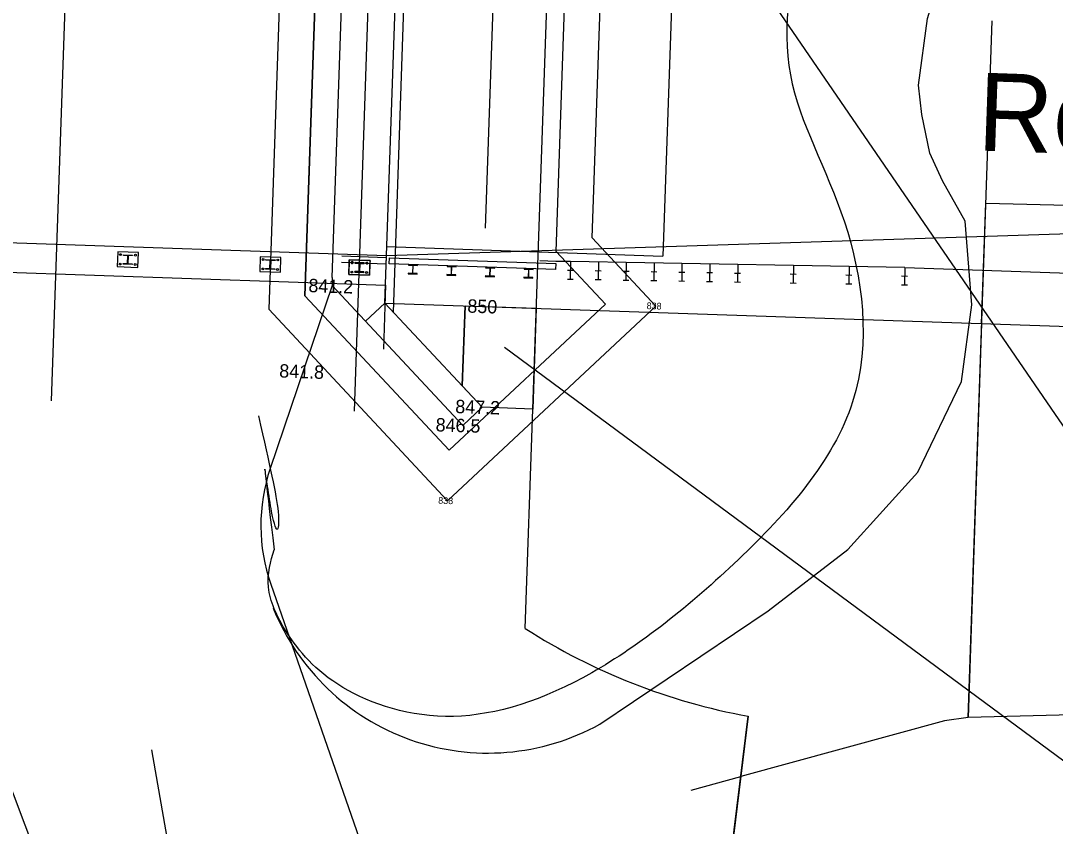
# Model space of a CAD drawing. Extents: x 2191309 to 2193046, y 863659 to 865133.
# Drawn here: x 2192668.4 to 2192726.5, y 863882.5 to 863927.7 of the extents above; entities that cross this region are included whole.
import ezdxf

# ---------------------------------------------------------------- set-up
doc = ezdxf.new("R2010")
doc.units = 0
for name, color, linetype in [('ANNOTATION', 7, 'Continuous'), ('D_Bridge_Abutment', 7, 'Continuous'), ('D_Bridge_Deck', 7, 'Continuous'), ('D_Bridge_Railing', 7, 'Continuous'), ('D_Bridge_Substructure_Hidden', 7, 'Continuous'), ('D_Guardrail_Beam_Lt', 7, 'Continuous'), ('D_Guardrail_Beam_Rt', 7, 'Continuous'), ('D_Roadway_Edge_Shoulder', 7, 'Continuous'), ('D_Roadway_Edge_TW', 7, 'Continuous'), ('D_Slope_Direction', 7, 'Continuous'), ('D_Slope_Toe', 7, 'Continuous'), ('DIMENSIONS', 7, 'Continuous'), ('H_V CONTROLS', 7, 'Continuous'), ('JUNK', 7, 'Continuous'), ('PATTERNING', 7, 'Continuous')]:
    doc.layers.add(name, color=color, linetype=linetype)

msp = doc.modelspace()

# ---------------------------------------------------------------- linework, layer by layer
at = {"layer": 'ANNOTATION'}
msp.add_line((2192706.024, 863884.486), (2192708.811, 863885.248), dxfattribs=at)
at = {"layer": 'D_Bridge_Abutment'}
for p, q in [((2192688.846, 863911.811), (2192690.012, 863945.791)), ((2192685.894, 863913.247), (2192685.878, 863912.792)), ((2192685.878, 863912.792), (2192693.209, 863904.94)), ((2192687.75, 863910.788), (2192688.846, 863911.811)), ((2192688.846, 863911.811), (2192694.306, 863905.964)), ((2192693.209, 863904.94), (2192694.306, 863905.964))]:
    msp.add_line(p, q, dxfattribs=at)
at = {"layer": 'D_Bridge_Deck'}
for p, q in [((2192651.959, 863915.745), (2192688.938, 863914.476)), ((2192651.902, 863914.08), (2192688.88, 863912.811))]:
    msp.add_line(p, q, dxfattribs=at)
at = {"layer": 'D_Bridge_Railing'}
for p, q in [((2192674.174, 863914.488), (2192674.175, 863914.525)), ((2192674.385, 863914.481), (2192674.174, 863914.488)), ((2192674.175, 863914.525), (2192674.685, 863914.507)), ((2192674.401, 863914.053), (2192674.415, 863914.449)), ((2192674.441, 863914.448), (2192674.427, 863914.052)), ((2192674.684, 863914.471), (2192674.473, 863914.478)), ((2192674.685, 863914.507), (2192674.684, 863914.471)), ((2192674.157, 863913.994), (2192674.158, 863914.03)), ((2192674.667, 863913.976), (2192674.157, 863913.994)), ((2192674.158, 863914.03), (2192674.37, 863914.023)), ((2192674.457, 863914.02), (2192674.668, 863914.013)), ((2192674.668, 863914.013), (2192674.667, 863913.976)), ((2192682.169, 863914.214), (2192682.171, 863914.25)), ((2192682.381, 863914.206), (2192682.169, 863914.214)), ((2192682.171, 863914.25), (2192682.681, 863914.233)), ((2192682.397, 863913.778), (2192682.41, 863914.175)), ((2192682.436, 863914.174), (2192682.423, 863913.777)), ((2192682.679, 863914.196), (2192682.468, 863914.203)), ((2192682.681, 863914.233), (2192682.679, 863914.196)), ((2192687.166, 863914.042), (2192687.168, 863914.079)), ((2192687.378, 863914.035), (2192687.166, 863914.042)), ((2192687.17, 863914.079), (2192687.168, 863914.041)), ((2192687.168, 863914.079), (2192687.678, 863914.061)), ((2192687.168, 863914.041), (2192687.378, 863914.034)), ((2192687.676, 863914.061), (2192687.17, 863914.079)), ((2192687.407, 863914.003), (2192687.393, 863913.607)), ((2192687.394, 863913.607), (2192687.407, 863914.003)), ((2192687.42, 863913.606), (2192687.434, 863914.002)), ((2192687.433, 863914.002), (2192687.42, 863913.606)), ((2192687.464, 863914.031), (2192687.675, 863914.023)), ((2192687.677, 863914.025), (2192687.465, 863914.032)), ((2192687.675, 863914.023), (2192687.676, 863914.061)), ((2192687.678, 863914.061), (2192687.677, 863914.025)), ((2192690.168, 863913.976), (2192690.166, 863913.938)), ((2192690.166, 863913.938), (2192690.377, 863913.931)), ((2192690.674, 863913.958), (2192690.168, 863913.976)), ((2192690.405, 863913.9), (2192690.392, 863913.504)), ((2192690.418, 863913.503), (2192690.432, 863913.899)), ((2192690.463, 863913.928), (2192690.673, 863913.92)), ((2192690.673, 863913.92), (2192690.674, 863913.958)), ((2192692.333, 863913.901), (2192692.332, 863913.863)), ((2192692.332, 863913.863), (2192692.542, 863913.856)), ((2192692.84, 863913.884), (2192692.333, 863913.901)), ((2192692.571, 863913.825), (2192692.557, 863913.429)), ((2192692.584, 863913.429), (2192692.597, 863913.825)), ((2192692.628, 863913.853), (2192692.838, 863913.846)), ((2192692.838, 863913.846), (2192692.84, 863913.884)), ((2192694.499, 863913.827), (2192694.497, 863913.789)), ((2192695.005, 863913.81), (2192694.499, 863913.827)), ((2192695.004, 863913.772), (2192695.005, 863913.81)), ((2192682.152, 863913.719), (2192682.154, 863913.756)), ((2192682.662, 863913.702), (2192682.152, 863913.719)), ((2192682.154, 863913.756), (2192682.365, 863913.748)), ((2192682.453, 863913.745), (2192682.664, 863913.738)), ((2192682.664, 863913.738), (2192682.662, 863913.702)), ((2192687.149, 863913.548), (2192687.151, 863913.584)), ((2192687.66, 863913.53), (2192687.149, 863913.548)), ((2192687.153, 863913.585), (2192687.151, 863913.547)), ((2192687.151, 863913.584), (2192687.362, 863913.577)), ((2192687.151, 863913.547), (2192687.658, 863913.53)), ((2192687.363, 863913.578), (2192687.153, 863913.585)), ((2192687.659, 863913.568), (2192687.449, 863913.575)), ((2192687.45, 863913.574), (2192687.661, 863913.567)), ((2192687.658, 863913.53), (2192687.659, 863913.568)), ((2192687.661, 863913.567), (2192687.66, 863913.53)), ((2192690.151, 863913.482), (2192690.15, 863913.444)), ((2192690.15, 863913.444), (2192690.656, 863913.427)), ((2192690.361, 863913.475), (2192690.151, 863913.482)), ((2192690.657, 863913.465), (2192690.447, 863913.472)), ((2192690.656, 863913.427), (2192690.657, 863913.465)), ((2192692.316, 863913.408), (2192692.315, 863913.37)), ((2192692.315, 863913.37), (2192692.821, 863913.353)), ((2192692.526, 863913.401), (2192692.316, 863913.408)), ((2192692.823, 863913.391), (2192692.612, 863913.398)), ((2192692.821, 863913.353), (2192692.823, 863913.391)), ((2192694.482, 863913.334), (2192694.48, 863913.296)), ((2192694.48, 863913.296), (2192694.987, 863913.278)), ((2192694.692, 863913.326), (2192694.482, 863913.334)), ((2192694.497, 863913.789), (2192694.707, 863913.782)), ((2192694.736, 863913.751), (2192694.722, 863913.355)), ((2192694.749, 863913.354), (2192694.763, 863913.75)), ((2192694.988, 863913.316), (2192694.778, 863913.323)), ((2192694.794, 863913.779), (2192695.004, 863913.772)), ((2192694.987, 863913.278), (2192694.988, 863913.316)), ((2192696.647, 863913.259), (2192696.646, 863913.221)), ((2192696.646, 863913.221), (2192697.152, 863913.204)), ((2192696.857, 863913.252), (2192696.647, 863913.259)), ((2192696.664, 863913.753), (2192696.663, 863913.715)), ((2192696.663, 863913.715), (2192696.873, 863913.708)), ((2192697.17, 863913.735), (2192696.664, 863913.753)), ((2192696.901, 863913.677), (2192696.888, 863913.281)), ((2192696.915, 863913.28), (2192696.928, 863913.676)), ((2192697.153, 863913.242), (2192696.943, 863913.249)), ((2192696.959, 863913.705), (2192697.169, 863913.697)), ((2192697.152, 863913.204), (2192697.153, 863913.242)), ((2192697.169, 863913.697), (2192697.17, 863913.735))]:
    msp.add_line(p, q, dxfattribs=at)
for points in [[(2192673.824, 863913.854), (2192674.99, 863913.814), (2192675.019, 863914.647), (2192673.853, 863914.687)], [(2192681.819, 863913.58), (2192682.985, 863913.54), (2192683.014, 863914.372), (2192681.848, 863914.412)], [(2192686.816, 863913.408), (2192687.982, 863913.368), (2192688.011, 863914.201), (2192686.845, 863914.241)]]:
    msp.add_lwpolyline(points, close=True, dxfattribs=at)
for points in [[(2192686.417, 863914.104), (2192688.922, 863914.018), (2192688.933, 863914.352), (2192686.429, 863914.438)], [(2192688.006, 863914.05), (2192687.982, 863913.368), (2192686.816, 863913.408), (2192686.84, 863914.09)], [(2192686.84, 863914.09), (2192686.845, 863914.241), (2192688.011, 863914.201), (2192688.006, 863914.05)], [(2192698.416, 863913.693), (2192689.088, 863914.013), (2192689.1, 863914.346), (2192698.428, 863914.026), (2192698.416, 863913.693)]]:
    msp.add_lwpolyline(points, dxfattribs=at)
for centre in [(2192674.014, 863914.53), (2192674.847, 863914.502), (2192673.996, 863913.999), (2192674.829, 863913.971), (2192682.009, 863914.256), (2192682.842, 863914.227), (2192687.006, 863914.084), (2192687.839, 863914.056), (2192681.991, 863913.725), (2192682.824, 863913.696), (2192686.988, 863913.553), (2192686.988, 863913.553), (2192687.821, 863913.525), (2192687.821, 863913.525)]:
    msp.add_circle(centre, 0.0521, dxfattribs=at)
for centre, radius, start, end in [((2192674.384, 863914.45), 0.0308, 358.03426, 88.03426), ((2192674.472, 863914.447), 0.0308, 88.03426, 178.03426), ((2192674.371, 863914.054), 0.0308, 268.03426, 358.03426), ((2192674.458, 863914.051), 0.0308, 178.03426, 268.03426), ((2192682.379, 863914.176), 0.0308, 358.03426, 88.03426), ((2192682.467, 863914.173), 0.0308, 88.03426, 178.03426), ((2192687.377, 863914.004), 0.0308, 358.03426, 88.03426), ((2192687.377, 863914.004), 0.0298, 358.03426, 88.03426), ((2192687.464, 863914.001), 0.0308, 88.03426, 178.03426), ((2192687.463, 863914.001), 0.0298, 88.03426, 178.03426), ((2192690.376, 863913.901), 0.0298, 358.03426, 88.03426), ((2192690.462, 863913.898), 0.0298, 88.03426, 178.03426), ((2192692.541, 863913.826), 0.0298, 358.03426, 88.03426), ((2192692.627, 863913.824), 0.0298, 88.03426, 178.03426), ((2192682.366, 863913.779), 0.0308, 268.03426, 358.03426), ((2192682.454, 863913.776), 0.0308, 178.03426, 268.03426), ((2192687.363, 863913.608), 0.0308, 268.03426, 358.03426), ((2192687.364, 863913.608), 0.0298, 268.03426, 358.03426), ((2192687.45, 863913.605), 0.0298, 178.03426, 268.03426), ((2192687.451, 863913.605), 0.0308, 178.03426, 268.03426), ((2192690.362, 863913.505), 0.0298, 268.03426, 358.03426), ((2192690.448, 863913.502), 0.0298, 178.03426, 268.03426), ((2192692.527, 863913.43), 0.0298, 268.03426, 358.03426), ((2192692.614, 863913.428), 0.0298, 178.03426, 268.03426), ((2192694.693, 863913.356), 0.0298, 268.03426, 358.03426), ((2192694.706, 863913.752), 0.0298, 358.03426, 88.03426), ((2192694.779, 863913.353), 0.0298, 178.03426, 268.03426), ((2192694.792, 863913.749), 0.0298, 88.03426, 178.03426), ((2192696.858, 863913.282), 0.0298, 268.03426, 358.03426), ((2192696.872, 863913.678), 0.0298, 358.03426, 88.03426), ((2192696.944, 863913.279), 0.0298, 178.03426, 268.03426), ((2192696.958, 863913.675), 0.0298, 88.03426, 178.03426)]:
    msp.add_arc(centre, radius, start, end, dxfattribs=at)
at = {"layer": 'D_Bridge_Substructure_Hidden'}
for p, q in [((2192689.329, 863911.294), (2192690.529, 863946.274)), ((2192684.394, 863913.298), (2192685.506, 863945.688)), ((2192685.894, 863913.247), (2192686.98, 863944.895)), ((2192698.451, 863914.711), (2192699.396, 863942.239)), ((2192705.395, 863942.095), (2192704.446, 863914.444)), ((2192688.955, 863914.976), (2192704.446, 863914.444)), ((2192698.451, 863914.711), (2192701.225, 863911.74)), ((2192684.358, 863912.223), (2192684.394, 863913.298)), ((2192684.358, 863912.223), (2192692.454, 863903.551)), ((2192692.454, 863903.551), (2192701.225, 863911.74))]:
    msp.add_line(p, q, dxfattribs=at)
at = {"layer": 'D_Guardrail_Beam_Lt'}
for p, q in [((2192698.432, 863914.15), (2192697.537, 863914.181)), ((2192699.265, 863914.136), (2192698.432, 863914.15)), ((2192699.265, 863914.136), (2192699.248, 863913.136)), ((2192711.763, 863913.92), (2192699.265, 863914.136)), ((2192700.827, 863914.109), (2192700.81, 863913.109)), ((2192702.39, 863914.082), (2192702.372, 863913.082)), ((2192703.952, 863914.055), (2192703.935, 863913.055)), ((2192705.514, 863914.028), (2192705.497, 863913.028)), ((2192707.076, 863914.001), (2192707.059, 863913.001)), ((2192708.639, 863913.974), (2192708.621, 863912.974)), ((2192711.763, 863913.92), (2192711.746, 863912.92)), ((2192718.012, 863913.812), (2192711.763, 863913.92)), ((2192714.888, 863913.866), (2192714.871, 863912.866)), ((2192718.012, 863913.812), (2192717.995, 863912.812)), ((2192699.423, 863913.633), (2192699.09, 863913.639)), ((2192700.985, 863913.606), (2192700.652, 863913.612)), ((2192702.548, 863913.579), (2192702.214, 863913.585)), ((2192704.11, 863913.552), (2192703.777, 863913.558)), ((2192705.672, 863913.525), (2192705.339, 863913.531)), ((2192707.234, 863913.498), (2192706.901, 863913.504)), ((2192708.797, 863913.471), (2192708.463, 863913.477)), ((2192711.921, 863913.417), (2192711.588, 863913.423)), ((2192715.046, 863913.363), (2192714.713, 863913.369)), ((2192718.17, 863913.309), (2192717.837, 863913.315)), ((2192699.415, 863913.133), (2192699.081, 863913.139)), ((2192700.977, 863913.106), (2192700.643, 863913.112)), ((2192702.539, 863913.079), (2192702.206, 863913.085)), ((2192704.101, 863913.052), (2192703.768, 863913.058)), ((2192705.664, 863913.025), (2192705.33, 863913.031)), ((2192707.226, 863912.998), (2192706.893, 863913.004)), ((2192708.788, 863912.971), (2192708.455, 863912.977)), ((2192711.913, 863912.917), (2192711.579, 863912.923)), ((2192715.037, 863912.863), (2192714.704, 863912.869)), ((2192718.162, 863912.809), (2192717.828, 863912.815))]:
    msp.add_line(p, q, dxfattribs=at)
for centre, start, end in [((2192687.006, 863914.084), 358.03426, 178.03426), ((2192687.006, 863914.084), 178.03426, 358.03426), ((2192687.839, 863914.056), 358.03426, 178.03426), ((2192687.839, 863914.056), 178.03426, 358.03426)]:
    msp.add_arc(centre, 0.0521, start, end, dxfattribs=at)
at = {"layer": 'D_Guardrail_Beam_Rt'}
msp.add_line((2192718.012, 863913.812), (2192739.874, 863913.062), dxfattribs=at)
at = {"layer": 'D_Roadway_Edge_Shoulder'}
msp.add_line((2192688.846, 863911.811), (2192739.796, 863910.063), dxfattribs=at)
msp.add_lwpolyline([(2192722.326, 863910.662), (2192722.558, 863917.417), (2192822.627, 863914.961), (2192822.472, 863908.633)], dxfattribs=at)
at = {"layer": 'D_Roadway_Edge_TW'}
msp.add_lwpolyline([(2192688.938, 863914.476), (2192738.911, 863916.096), (2192747.181, 863915.813)], dxfattribs=at)
at = {"layer": 'D_Slope_Direction'}
msp.add_line((2192722.326, 863910.662), (2192721.567, 863888.553), dxfattribs=at)
at = {"layer": 'D_Slope_Toe'}
for p, q in [((2192685.878, 863912.792), (2192682.41, 863902.527)), ((2192693.209, 863904.94), (2192685.878, 863912.792)), ((2192694.306, 863905.964), (2192693.209, 863904.94))]:
    msp.add_line(p, q, dxfattribs=at)
msp.add_lwpolyline([(2192693.343, 863911.657), (2192697.341, 863911.52), (2192697.147, 863905.866), (2192694.306, 863905.964), (2192693.189, 863907.16)], close=True, dxfattribs=at)
for points in [[(2192696.724, 863893.55), (2192697.147, 863905.866), (2192694.306, 863905.964)], [(2192682.441, 863896.036), (2192688.006, 863880.062), (2192691.157, 863872.616)], [(2192747.062, 863892.868), (2192739.054, 863889.015), (2192721.567, 863888.553), (2192720.247, 863888.374), (2192708.811, 863885.248)], [(2192675.792, 863863.139), (2192675.037, 863865.579), (2192666.083, 863889.336)], [(2192695.837, 863868.772), (2192698.043, 863870.031), (2192707.811, 863877.092), (2192709.226, 863888.633)]]:
    msp.add_lwpolyline(points, dxfattribs=at)
for centre, radius, start, end in [((2192691.884, 863899.326), 10, 161.33248, 199.21069), ((2192715.548, 863923.057), 35, 237.4643, 259.59275)]:
    msp.add_arc(centre, radius, start, end, dxfattribs=at)
at = {"layer": 'DIMENSIONS'}
for p, q in [((2192687.137, 863905.744), (2192690.356, 863999.536)), ((2192753.012, 863866.823), (2192697.244, 863948.19))]:
    msp.add_line(p, q, dxfattribs=at)
for points in [[(2192758.009, 863866.651), (2192753.012, 863866.823), (2192695.557, 863909.317)], [(2192680.338, 863832.179), (2192685.335, 863832.007), (2192675.775, 863886.75)]]:
    msp.add_lwpolyline(points, dxfattribs=at)
at = {"layer": 'H_V CONTROLS'}
msp.add_line((2192709.226, 863888.633), (2192707.811, 863877.092), dxfattribs=at)
at = {"layer": 'JUNK'}
for p, q in [((2192670.147, 863906.327), (2192672.277, 863968.379)), ((2192683.536, 863946.585), (2192682.33, 863911.463)), ((2192685.506, 863945.688), (2192684.358, 863912.223)), ((2192694.494, 863916.019), (2192695.358, 863941.206)), ((2192700.478, 863915.471), (2192701.366, 863941.343)), ((2192697.147, 863905.866), (2192697.924, 863928.51)), ((2192721.567, 863888.553), (2192722.909, 863927.652)), ((2192704.052, 863911.643), (2192700.478, 863915.471)), ((2192684.358, 863912.223), (2192692.454, 863903.551)), ((2192692.357, 863900.724), (2192704.052, 863911.643)), ((2192682.33, 863911.463), (2192692.357, 863900.724))]:
    msp.add_line(p, q, dxfattribs=at)
msp.add_lwpolyline([(2192700.907, 863888.185), (2192710.351, 863894.547), (2192714.819, 863897.982), (2192718.745, 863902.331), (2192721.192, 863907.418), (2192721.778, 863911.717), (2192721.411, 863916.403), (2192720.124, 863918.666), (2192719.425, 863920.225), (2192718.977, 863922.395), (2192718.783, 863924.044), (2192719.287, 863927.776), (2192720.883, 863932.894), (2192722.2, 863937.154), (2192722.909, 863941.723)], dxfattribs=at)
msp.add_arc((2192694.624, 863899.548), 12.983, 201.91629, 298.94012, dxfattribs=at)
for points in [[(2192714.042, 863951.037), (2192714.546, 863950.448), (2192715.819, 863948.853), (2192718.033, 863945.378), (2192718.005, 863938.963), (2192712.045, 863933.513), (2192710.6, 863924.308), (2192715.126, 863916.992), (2192716.664, 863905.894), (2192708.759, 863897.065), (2192700.367, 863890.385), (2192692.486, 863887.826), (2192685.832, 863890.057), (2192683.087, 863893.445), (2192682.032, 863895.929), (2192682.445, 863897.338), (2192682.626, 863897.958)], [(2192681.75, 863905.491), (2192682.39, 863902.607), (2192683.113, 863899.635), (2192682.626, 863897.958), (2192681.75, 863905.491), (2192682.626, 863897.958)]]:
    msp.add_open_spline(points, degree=3, dxfattribs=at)
at = {"layer": 'PATTERNING'}
for p, q in [((2192688.88, 863912.811), (2192688.758, 863909.233)), ((2192693.343, 863911.657), (2192693.189, 863907.16)), ((2192697.341, 863911.52), (2192697.147, 863905.866))]:
    msp.add_line(p, q, dxfattribs=at)

# ---------------------------------------------------------------- texts
at = {"layer": 'ANNOTATION'}
msp.add_text('Route 212', height=4.375, rotation=358.03426, dxfattribs=at).set_placement((2192722.054, 863920.371))
at = {"layer": 'JUNK'}
for s, height, p in [('841.2', 0.75, (2192684.545, 863912.428)), ('850', 0.75, (2192693.464, 863911.278)), ('838', 0.375, (2192703.526, 863911.474)), ('841.8', 0.75, (2192682.908, 863907.638)), ('847.2', 0.75, (2192692.785, 863905.641)), ('846.5', 0.75, (2192691.682, 863904.617)), ('838', 0.375, (2192691.831, 863900.555))]:
    msp.add_text(s, height=height, rotation=358.03426, dxfattribs=at).set_placement(p)

doc.saveas('drawing.dxf')
